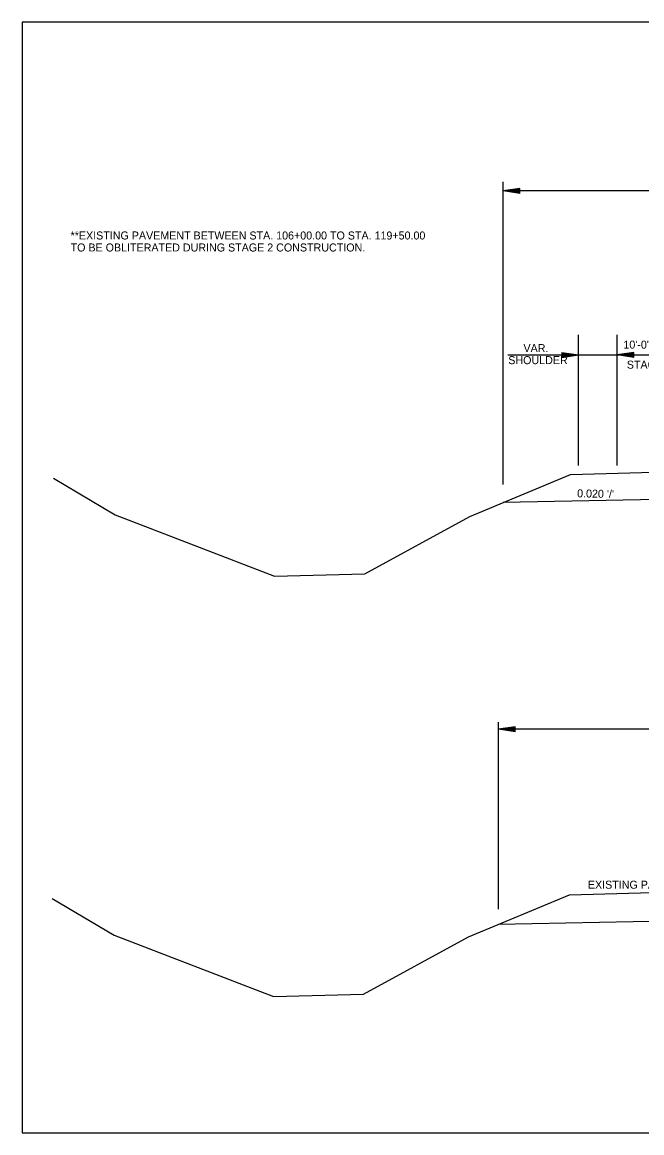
# Model space of a CAD drawing. Extents: x 1807779 to 1818251, y 673292 to 678849.
# Drawn here: x 1812651 to 1813209, y 676380 to 677379 of the extents above; entities that cross this region are included whole.
import ezdxf

# ---------------------------------------------------------------- set-up
doc = ezdxf.new("R2010")
doc.units = 0
for name, color, linetype in [('Default', 7, 'Continuous'), ('Dimensions', 7, 'Continuous'), ('DSN_DRFT_Guideline-No-Plot', 7, 'Continuous'), ('EX_TERRAIN', 7, 'Continuous')]:
    doc.layers.add(name, color=color, linetype=linetype)

msp = doc.modelspace()

# ---------------------------------------------------------------- linework, layer by layer
at = {"layer": 'Default'}
for p, q in [((1813222.83, 676949.54), (1813083.74, 676946.76)), ((1813324.59, 676572.23), (1813079.53, 676567.33))]:
    msp.add_line(p, q, dxfattribs=at)
at = {"layer": 'Dimensions'}
for p, q in [((1813083.74, 676963.08), (1813083.74, 677235.25)), ((1813098.74, 677229.42), (1813083.74, 677227.17)), ((1813487.67, 677227.17), (1813083.74, 677227.17)), ((1813098.74, 677224.92), (1813083.74, 677227.17)), ((1813098.74, 677229.05), (1813086.24, 677227.17)), ((1813098.74, 677225.3), (1813086.24, 677227.17)), ((1813098.74, 677228.67), (1813088.82, 677227.17)), ((1813098.74, 677225.68), (1813088.82, 677227.17)), ((1813098.74, 677228.29), (1813091.32, 677227.17)), ((1813098.74, 677226.06), (1813091.32, 677227.17)), ((1813098.74, 677227.91), (1813093.86, 677227.17)), ((1813098.74, 677226.45), (1813093.86, 677227.17)), ((1813098.74, 677227.53), (1813096.37, 677227.17)), ((1813098.74, 677226.82), (1813096.37, 677227.17)), ((1813098.74, 677224.92), (1813098.74, 677229.42)), ((1813151.45, 676980.16), (1813151.45, 677097.63)), ((1813186.49, 676980.16), (1813186.49, 677097.63)), ((1813136.45, 677081.84), (1813151.45, 677079.59)), ((1813136.45, 677081.84), (1813136.45, 677077.34)), ((1813136.45, 677081.46), (1813148.95, 677079.59)), ((1813201.49, 677081.84), (1813186.49, 677079.59)), ((1813201.49, 677081.46), (1813189, 677079.59)), ((1813201.49, 677077.34), (1813201.49, 677081.84)), ((1813087.87, 677079.59), (1813286.49, 677079.59)), ((1813136.45, 677081.08), (1813146.37, 677079.59)), ((1813136.45, 677080.71), (1813143.87, 677079.59)), ((1813136.45, 677080.32), (1813141.33, 677079.59)), ((1813136.45, 677079.94), (1813138.82, 677079.59)), ((1813136.45, 677077.34), (1813151.45, 677079.59)), ((1813136.45, 677078.85), (1813141.33, 677079.59)), ((1813136.45, 677078.1), (1813146.37, 677079.59)), ((1813136.45, 677077.71), (1813148.95, 677079.59)), ((1813136.45, 677078.47), (1813143.87, 677079.59)), ((1813136.45, 677079.24), (1813138.82, 677079.59)), ((1813201.49, 677077.34), (1813186.49, 677079.59)), ((1813201.49, 677077.71), (1813189, 677079.59)), ((1813201.49, 677081.08), (1813191.58, 677079.59)), ((1813201.49, 677078.1), (1813191.58, 677079.59)), ((1813201.49, 677080.71), (1813194.08, 677079.59)), ((1813201.49, 677078.47), (1813194.08, 677079.59)), ((1813201.49, 677080.32), (1813196.62, 677079.59)), ((1813201.49, 677078.86), (1813196.62, 677079.59)), ((1813201.49, 677079.94), (1813199.12, 677079.59)), ((1813201.49, 677079.24), (1813199.12, 677079.59)), ((1813079.53, 676580.92), (1813079.53, 676749.35)), ((1813094.53, 676745.16), (1813079.53, 676742.91)), ((1813479.43, 676742.91), (1813079.53, 676742.91)), ((1813094.53, 676740.66), (1813079.53, 676742.91)), ((1813094.53, 676744.78), (1813082.04, 676742.91)), ((1813094.53, 676741.03), (1813082.04, 676742.91)), ((1813094.53, 676744.4), (1813084.62, 676742.91)), ((1813094.53, 676741.42), (1813084.62, 676742.91)), ((1813094.53, 676744.03), (1813087.12, 676742.91)), ((1813094.53, 676741.79), (1813087.12, 676742.91)), ((1813094.53, 676743.64), (1813089.66, 676742.91)), ((1813094.53, 676742.18), (1813089.66, 676742.91)), ((1813094.53, 676743.26), (1813092.16, 676742.91)), ((1813094.53, 676742.56), (1813092.16, 676742.91)), ((1813094.53, 676740.66), (1813094.53, 676745.16))]:
    msp.add_line(p, q, dxfattribs=at)
at = {"layer": 'DSN_DRFT_Guideline-No-Plot'}
msp.add_lwpolyline([(1812650.63, 676379.88), (1814300.63, 676379.88), (1814300.63, 677378.94), (1812650.63, 677378.94)], close=True, dxfattribs=at)
at = {"layer": 'EX_TERRAIN'}
for points in [[(1812678.82, 676968.89), (1812734.48, 676935.93), (1812877.87, 676880.69), (1812959.16, 676882.83), (1813053.74, 676934.27), (1813144.45, 676972.05), (1813219.03, 676974.2), (1813299.21, 676975.27), (1813459.2, 676973.13), (1813487.67, 676972.49), (1813516, 676968.9), (1813566.57, 676954.47), (1813614.02, 676941.38), (1813728.73, 676880.37), (1813806.18, 676862.53), (1813861.67, 676857.88), (1813918.12, 676853.04), (1814104.93, 676852.07), (1814246.73, 676850.15)], [(1812677.73, 676590.75), (1812733.39, 676557.8), (1812876.78, 676502.56), (1812958.07, 676504.7), (1813052.65, 676556.13), (1813143.36, 676593.92), (1813217.94, 676596.07), (1813298.12, 676597.14), (1813458.11, 676595), (1813486.58, 676594.36), (1813514.91, 676590.77), (1813565.47, 676576.34), (1813612.93, 676563.25), (1813727.64, 676502.24), (1813805.09, 676484.4), (1813860.58, 676479.74), (1813917.03, 676474.91), (1814103.84, 676473.94), (1814245.64, 676472.02)]]:
    msp.add_lwpolyline(points, dxfattribs=at)

# ---------------------------------------------------------------- texts
at = {"layer": 'Dimensions'}
for s, p in [('**EXISTING PAVEMENT BETWEEN STA. 106+00.00 TO STA. 119+50.00 ', (1812694.22, 677183.48)), ('TO BE OBLITERATED DURING STAGE 2 CONSTRUCTION.', (1812694.22, 677172.68)), ('10\'-0" EXIST. LANE', (1813191.99, 677085.28)), ('VAR.', (1813101.99, 677082.14)), ('SHOULDER', (1813088.32, 677071.34)), ('STAGE 1 TRAFFIC', (1813195.06, 677067.28)), ('EXISTING PAVEMENT TO BE OBLITERATED', (1813160, 676599.45))]:
    msp.add_text(s, height=7.2, dxfattribs=at).set_placement(p)
msp.add_text("0.020 '/'", height=7.2, rotation=358.75932, dxfattribs=at).set_placement((1813150.26, 676951.58))

doc.saveas('drawing.dxf')
